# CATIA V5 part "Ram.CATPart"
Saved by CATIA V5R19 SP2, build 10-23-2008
Part number: Ram
Bounding box of the stored display mesh (mm): x -40 to 40, y -40 to 240, z -40 to 160
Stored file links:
  D:\Catia\Flexible-rigid\Ram.CATPart
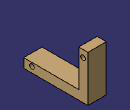
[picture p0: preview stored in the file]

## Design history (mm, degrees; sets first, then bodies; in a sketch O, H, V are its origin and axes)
AxisSystem1: origin (0, 0, 0), X (1, 0, 0), Y (0, 1, 0), Z (0, 0, 1)
Body1 (main body)
  Sketch1 on YZ plane of AxisSystem1, origin (0, 0, 0), H (0, 1, 0), V (0, 0, 1)
    point P1 (-40, 0)
    line L1 (-40, 0) -> (200, 0)
    line L2 (200, 0) -> (200, 160)
    coincidence: P1 H
    horizontal: L1 H
    vertical: L2 V
  Pad1: profile Sketch1, direction (1, 0, 0), length 40, mirrored extent, thin wall 0, second thickness 40
  Sketch2 on end face of Pad1, origin (40, 218.683, 129.1257), H (0, 1, 0), V (0, 0, 1)
    point P1 (0, 0)
  Hole1: placed by Sketch2, at (40, 218.683, 129.1257) direction (-1, 0, 0), diameter 20, through (limit type 6)
  Sketch3 on end face of Pad1, origin (40, -4.2318, -25.0394), H (0, 1, 0), V (0, 0, 1)
    point P1 (0, 10)
  Hole2: placed by Sketch3, at (40, -4.2318, -15.0394) direction (-1, 0, 0), diameter 20, through (limit type 6)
